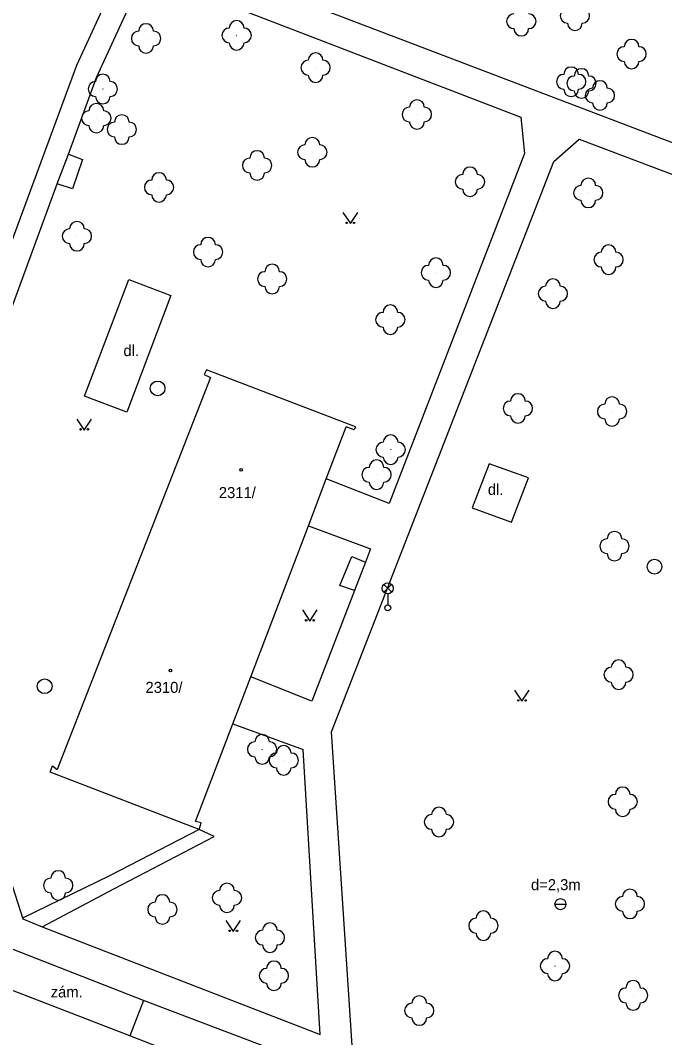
# Model space of a CAD drawing. Extents: x -737812 to -729375, y -1123000 to -1115500.
# Drawn here: x -736618.5 to -736574.7, y -1118642.1 to -1118573.1 of the extents above; entities that cross this region are included whole.
import ezdxf

# ---------------------------------------------------------------- set-up
doc = ezdxf.new("R2010")
doc.units = 0
for name, color, linetype in [('Doplněk polohopisu', 7, 'Continuous'), ('Doplňkové značky', 7, 'Continuous'), ('Komunikace', 7, 'Continuous'), ('Pomocné popisy', 7, 'Continuous'), ('Povr_ zn_ inž_ sítí - el_', 7, 'Continuous'), ('Povr_ zn_ inž_ sítí - kan_', 7, 'Continuous'), ('Stavební objekty', 7, 'Continuous'), ('Zeleň', 7, 'Continuous'), ('Značky druhů budov', 7, 'Continuous'), ('Značky druhů pozemků', 7, 'Continuous'), ('Čísla popisná', 7, 'Continuous')]:
    doc.layers.add(name, color=color, linetype=linetype)

msp = doc.modelspace()

# ---------------------------------------------------------------- linework, layer by layer
at = {"layer": 'Doplněk polohopisu'}
for p, q in [((-736613.29, -1118576.93), (-736610.8, -1118571.51)), ((-736615.21, -1118582.13), (-736613.29, -1118576.93)), ((-736615.96, -1118584.14), (-736615.21, -1118582.13)), ((-736625.78, -1118610.65), (-736615.96, -1118584.14)), ((-736598.91, -1118607.35), (-736594.68, -1118608.93)), ((-736594.68, -1118608.93), (-736595.02, -1118609.82)), ((-736595.02, -1118609.82), (-736595.78, -1118611.76)), ((-736625.78, -1118610.65), (-736618.31, -1118634.04)), ((-736595.78, -1118611.76), (-736598.67, -1118619.25)), ((-736598.67, -1118619.25), (-736602.82, -1118617.61)), ((-736598.11, -1118641.88), (-736599.27, -1118622.55)), ((-736618.31, -1118634.04), (-736617, -1118634.57)), ((-736617, -1118634.57), (-736598.11, -1118641.88)), ((-736597.79, -1118644.24), (-736610.11, -1118639.58)), ((-736598.73, -1118646.75), (-736611.04, -1118641.97))]:
    msp.add_line(p, q, dxfattribs=at)
for points in [[(-736611.83, -1118565.83), (-736611.08, -1118566.66), (-736610.89, -1118567.95), (-736614.66, -1118576.12), (-736617.94, -1118585), (-736626.76, -1118608.86)], [(-736573.82, -1118581.5), (-736600.76, -1118571.22)], [(-736605.73, -1118571.43), (-736584.49, -1118579.63), (-736584.22, -1118582.09), (-736593.43, -1118605.85), (-736597.7, -1118604.18)], [(-736595.94, -1118642.63), (-736597.33, -1118621.34), (-736582.25, -1118582.62), (-736580.51, -1118581.12), (-736573.74, -1118583.67)], [(-736615.21, -1118582.13), (-736614.24, -1118582.49), (-736614.92, -1118584.49), (-736615.96, -1118584.14)], [(-736611.25, -1118599.64), (-736614.12, -1118598.55), (-736611.11, -1118590.63), (-736608.24, -1118591.73), (-736611.25, -1118599.64)], [(-736587.78, -1118606.13), (-736585.11, -1118607.11), (-736583.97, -1118604.11), (-736586.62, -1118603.16), (-736587.78, -1118606.13)], [(-736595.78, -1118611.76), (-736596.77, -1118611.42), (-736595.95, -1118609.44), (-736595.02, -1118609.82)], [(-736604.04, -1118620.81), (-736599.27, -1118622.55)], [(-736617, -1118634.57), (-736612.08, -1118631.98), (-736605.3, -1118628.44), (-736606.32, -1118627.98), (-736612.41, -1118631.12), (-736618.33, -1118633.99)], [(-736610.11, -1118639.58), (-736611.04, -1118641.97)]]:
    msp.add_lwpolyline(points, dxfattribs=at)
at = {"layer": 'Doplňkové značky'}
msp.add_line((-736582.165, -1118633.04), (-736581.415, -1118633.04), dxfattribs=at)
msp.add_circle((-736581.79, -1118633.04), 0.375, dxfattribs=at)
at = {"layer": 'Komunikace'}
for points in [[(-736610.11, -1118639.58), (-736618.95, -1118636.11)], [(-736611.04, -1118641.97), (-736619.91, -1118638.55)]]:
    msp.add_lwpolyline(points, dxfattribs=at)
at = {"layer": 'Povr_ zn_ inž_ sítí - el_'}
for p, q in [((-736593.784, -1118611.868), (-736593.256, -1118611.34)), ((-736593.248, -1118611.865), (-736593.776, -1118611.336)), ((-736593.52, -1118611.98), (-736593.52, -1118612.73))]:
    msp.add_line(p, q, dxfattribs=at)
for centre, radius in [((-736593.52, -1118611.605), 0.375), ((-736593.52, -1118612.93), 0.2)]:
    msp.add_circle(centre, radius, dxfattribs=at)
at = {"layer": 'Povr_ zn_ inž_ sítí - kan_'}
for centre in [(-736609.15, -1118598.03), (-736575.4, -1118610.13), (-736616.82, -1118618.25)]:
    msp.add_circle(centre, 0.5, dxfattribs=at)
at = {"layer": 'Stavební objekty'}
for points in [[(-736605.84, -1118596.78), (-736605.99, -1118597.08)], [(-736595.7, -1118600.65), (-736605.84, -1118596.78)], [(-736605.56, -1118597.3), (-736615.97, -1118623.9)], [(-736605.99, -1118597.08), (-736605.56, -1118597.3)], [(-736606.57, -1118627.43), (-736604.04, -1118620.81), (-736602.82, -1118617.61), (-736598.91, -1118607.35), (-736597.7, -1118604.18), (-736596.34, -1118600.64)], [(-736595.79, -1118600.85), (-736596.34, -1118600.64)], [(-736595.7, -1118600.65), (-736595.79, -1118600.85)], [(-736616.45, -1118624.08), (-736616.29, -1118623.66)], [(-736616.29, -1118623.66), (-736615.97, -1118623.9)], [(-736606.32, -1118627.98), (-736616.45, -1118624.08)], [(-736606.19, -1118627.53), (-736606.57, -1118627.43)], [(-736606.32, -1118627.98), (-736606.19, -1118627.53)]]:
    msp.add_lwpolyline(points, dxfattribs=at)
at = {"layer": 'Zeleň'}
for centre in [(-736584.45, -1118573.11), (-736603.78, -1118574.07), (-736609.93, -1118574.28), (-736576.96, -1118575.34), (-736598.42, -1118576.26), (-736581.06, -1118577.22), (-736580.36, -1118577.33), (-736612.87, -1118577.71), (-736579.11, -1118578.15), (-736591.54, -1118579.44), (-736613.31, -1118579.69), (-736611.58, -1118580.46), (-736598.64, -1118582), (-736602.39, -1118582.9), (-736609.05, -1118584.39), (-736587.93, -1118584.01), (-736579.9, -1118584.76), (-736614.63, -1118587.7), (-736605.72, -1118588.78), (-736578.52, -1118589.29), (-736601.37, -1118590.61), (-736590.25, -1118590.18), (-736582.3, -1118591.6), (-736593.34, -1118593.37), (-736584.68, -1118599.39), (-736578.28, -1118599.6), (-736593.32, -1118602.19), (-736594.28, -1118603.89), (-736578.12, -1118608.74), (-736577.84, -1118617.46), (-736602.05, -1118622.53), (-736600.58, -1118623.28), (-736577.56, -1118626.09), (-736590.04, -1118627.46), (-736615.9, -1118631.77), (-736604.44, -1118632.61), (-736608.82, -1118633.4), (-736577.07, -1118633.02), (-736587.02, -1118634.5), (-736601.52, -1118635.31), (-736582.16, -1118637.24), (-736601.25, -1118637.9), (-736576.85, -1118639.23), (-736591.38, -1118640.26)]:
    msp.add_circle(centre, 0.0005, dxfattribs=at)
for centre, start, end in [((-736584.95, -1118573.11), 89.99999, 269.99999), ((-736583.95, -1118573.11), 270, 89.99999), ((-736581.31, -1118572.74), 89.99999, 269.99999), ((-736580.31, -1118572.74), 270, 89.99999), ((-736609.93, -1118573.78), 0, 179.99999), ((-736603.78, -1118573.57), 360, 179.99999), ((-736580.81, -1118573.24), 179.99999, 359.99999), ((-736610.43, -1118574.28), 89.99999, 269.99999), ((-736609.43, -1118574.28), 270, 89.99999), ((-736604.28, -1118574.07), 89.99999, 269.99999), ((-736603.28, -1118574.07), 270, 89.99999), ((-736584.45, -1118573.61), 179.99999, 359.99999), ((-736609.93, -1118574.78), 179.99999, 359.99999), ((-736603.78, -1118574.57), 179.99999, 359.99999), ((-736576.96, -1118574.84), 360, 179.99999), ((-736598.42, -1118575.76), 360, 179.99999), ((-736577.46, -1118575.34), 89.99999, 269.99999), ((-736576.46, -1118575.34), 270, 89.99999), ((-736598.92, -1118576.26), 89.99999, 269.99999), ((-736597.92, -1118576.26), 270, 89.99999), ((-736576.96, -1118575.84), 179.99999, 359.99999), ((-736612.87, -1118577.21), 360, 179.99999), ((-736598.42, -1118576.76), 179.99999, 359.99999), ((-736581.56, -1118577.22), 89.99999, 269.99999), ((-736581.06, -1118576.72), 360, 179.99999), ((-736580.86, -1118577.33), 89.99999, 269.99999), ((-736580.36, -1118576.83), 360, 179.99999), ((-736580.56, -1118577.22), 270, 89.99999), ((-736579.86, -1118577.33), 270, 89.99999), ((-736613.37, -1118577.71), 89.99999, 269.99999), ((-736612.37, -1118577.71), 270, 89.99999), ((-736579.11, -1118577.65), 360, 179.99999), ((-736612.87, -1118578.21), 179.99999, 359.99999), ((-736581.06, -1118577.72), 179.99999, 359.99999), ((-736580.36, -1118577.83), 179.99999, 359.99999), ((-736579.61, -1118578.15), 89.99999, 269.99999), ((-736578.61, -1118578.15), 270, 89.99999), ((-736613.31, -1118579.19), 360, 179.99999), ((-736591.54, -1118578.94), 360, 179.99999), ((-736579.11, -1118578.65), 179.99999, 359.99999), ((-736613.81, -1118579.69), 89.99999, 269.99999), ((-736612.81, -1118579.69), 270, 89.99999), ((-736611.58, -1118579.96), 0, 179.99999), ((-736592.04, -1118579.44), 89.99999, 269.99999), ((-736591.04, -1118579.44), 270, 89.99999), ((-736613.31, -1118580.19), 179.99999, 359.99999), ((-736612.08, -1118580.46), 89.99999, 269.99999), ((-736611.08, -1118580.46), 270, 89.99999), ((-736591.54, -1118579.94), 179.99999, 359.99999), ((-736611.58, -1118580.96), 179.99999, 359.99999), ((-736599.14, -1118582), 89.99999, 269.99999), ((-736598.64, -1118581.5), 360, 179.99999), ((-736598.14, -1118582), 270, 89.99999), ((-736602.39, -1118582.4), 360, 179.99999), ((-736602.89, -1118582.9), 89.99999, 269.99999), ((-736601.89, -1118582.9), 270, 89.99999), ((-736598.64, -1118582.5), 179.99999, 359.99999), ((-736587.93, -1118583.51), 360, 179.99999), ((-736609.05, -1118583.89), 360, 179.99999), ((-736602.39, -1118583.4), 179.99999, 359.99999), ((-736588.43, -1118584.01), 89.99999, 269.99999), ((-736587.43, -1118584.01), 270, 89.99999), ((-736579.9, -1118584.26), 360, 179.99999), ((-736609.55, -1118584.39), 89.99999, 269.99999), ((-736608.55, -1118584.39), 270, 89.99999), ((-736580.4, -1118584.76), 89.99999, 269.99999), ((-736579.4, -1118584.76), 270, 89.99999), ((-736609.05, -1118584.89), 179.99999, 359.99999), ((-736587.93, -1118584.51), 179.99999, 359.99999), ((-736579.9, -1118585.26), 179.99999, 359.99999), ((-736615.13, -1118587.7), 89.99999, 269.99999), ((-736614.63, -1118587.2), 0, 179.99999), ((-736614.13, -1118587.7), 270, 89.99999), ((-736605.72, -1118588.28), 0, 179.99999), ((-736614.63, -1118588.2), 179.99999, 359.99999), ((-736606.22, -1118588.78), 89.99999, 269.99999), ((-736605.22, -1118588.78), 270, 89.99999), ((-736578.52, -1118588.79), 360, 179.99999), ((-736605.72, -1118589.28), 179.99999, 359.99999), ((-736590.25, -1118589.68), 360, 179.99999), ((-736579.02, -1118589.29), 89.99999, 269.99999), ((-736578.02, -1118589.29), 270, 89.99999), ((-736601.37, -1118590.11), 0, 179.99999), ((-736590.75, -1118590.18), 89.99999, 269.99999), ((-736589.75, -1118590.18), 270, 89.99999), ((-736578.52, -1118589.79), 179.99999, 359.99999), ((-736601.87, -1118590.61), 89.99999, 269.99999), ((-736600.87, -1118590.61), 270, 89.99999), ((-736582.3, -1118591.1), 360, 179.99999), ((-736601.37, -1118591.11), 179.99999, 359.99999), ((-736590.25, -1118590.68), 179.99999, 359.99999), ((-736582.8, -1118591.6), 89.99999, 269.99999), ((-736581.8, -1118591.6), 270, 89.99999), ((-736593.34, -1118592.87), 360, 179.99999), ((-736582.3, -1118592.1), 179.99999, 359.99999), ((-736593.84, -1118593.37), 89.99999, 269.99999), ((-736592.84, -1118593.37), 270, 89.99999), ((-736593.34, -1118593.87), 179.99999, 359.99999), ((-736585.18, -1118599.39), 89.99999, 269.99999), ((-736584.68, -1118598.89), 360, 179.99999), ((-736584.18, -1118599.39), 270, 89.99999), ((-736578.28, -1118599.1), 360, 179.99999), ((-736578.78, -1118599.6), 89.99999, 269.99999), ((-736577.78, -1118599.6), 270, 89.99999), ((-736584.68, -1118599.89), 179.99999, 359.99999), ((-736578.28, -1118600.1), 179.99999, 359.99999), ((-736593.82, -1118602.19), 89.99999, 269.99999), ((-736593.32, -1118601.69), 360, 179.99999), ((-736592.82, -1118602.19), 270, 89.99999), ((-736594.28, -1118603.39), 360, 179.99999), ((-736593.32, -1118602.69), 179.99999, 359.99999), ((-736594.78, -1118603.89), 89.99999, 269.99999), ((-736593.78, -1118603.89), 270, 89.99999), ((-736594.28, -1118604.39), 179.99999, 359.99999), ((-736578.12, -1118608.24), 360, 179.99999), ((-736578.62, -1118608.74), 89.99999, 269.99999), ((-736577.62, -1118608.74), 270, 89.99999), ((-736578.12, -1118609.24), 179.99999, 359.99999), ((-736577.84, -1118616.96), 360, 179.99999), ((-736578.34, -1118617.46), 89.99999, 269.99999), ((-736577.34, -1118617.46), 270, 89.99999), ((-736577.84, -1118617.96), 179.99999, 359.99999), ((-736602.05, -1118622.03), 360, 179.99999), ((-736602.55, -1118622.53), 89.99999, 269.99999), ((-736601.55, -1118622.53), 270, 89.99999), ((-736600.58, -1118622.78), 360, 179.99999), ((-736602.05, -1118623.03), 179.99999, 359.99999), ((-736601.08, -1118623.28), 89.99999, 269.99999), ((-736600.08, -1118623.28), 270, 89.99999), ((-736600.58, -1118623.78), 179.99999, 359.99999), ((-736577.56, -1118625.59), 360, 179.99999), ((-736578.06, -1118626.09), 89.99999, 269.99999), ((-736577.06, -1118626.09), 270, 89.99999), ((-736590.04, -1118626.96), 360, 179.99999), ((-736590.54, -1118627.46), 89.99999, 269.99999), ((-736589.54, -1118627.46), 270, 89.99999), ((-736577.56, -1118626.59), 179.99999, 359.99999), ((-736590.04, -1118627.96), 179.99999, 359.99999), ((-736616.4, -1118631.77), 89.99999, 269.99999), ((-736615.9, -1118631.27), 360, 179.99999), ((-736615.4, -1118631.77), 270, 89.99999), ((-736604.44, -1118632.11), 360, 179.99999), ((-736577.07, -1118632.52), 360, 179.99999), ((-736615.9, -1118632.27), 179.99999, 359.99999), ((-736608.82, -1118632.9), 360, 179.99999), ((-736604.94, -1118632.61), 89.99999, 269.99999), ((-736603.94, -1118632.61), 270, 89.99999), ((-736577.57, -1118633.02), 89.99999, 269.99999), ((-736576.57, -1118633.02), 270, 89.99999), ((-736609.32, -1118633.4), 89.99999, 269.99999), ((-736608.32, -1118633.4), 270, 89.99999), ((-736604.44, -1118633.11), 179.99999, 359.99999), ((-736608.82, -1118633.9), 179.99999, 359.99999), ((-736587.52, -1118634.5), 89.99999, 269.99999), ((-736587.02, -1118634), 360, 179.99999), ((-736586.52, -1118634.5), 270, 89.99999), ((-736577.07, -1118633.52), 179.99999, 359.99999), ((-736602.02, -1118635.31), 89.99999, 269.99999), ((-736601.52, -1118634.81), 360, 179.99999), ((-736601.02, -1118635.31), 270, 89.99999), ((-736587.02, -1118635), 179.99999, 359.99999), ((-736601.52, -1118635.81), 179.99999, 359.99999), ((-736601.25, -1118637.4), 360, 179.99999), ((-736582.66, -1118637.24), 89.99999, 269.99999), ((-736582.16, -1118636.74), 360, 179.99999), ((-736581.66, -1118637.24), 270, 89.99999), ((-736601.75, -1118637.9), 89.99999, 269.99999), ((-736600.75, -1118637.9), 270, 89.99999), ((-736582.16, -1118637.74), 179.99999, 359.99999), ((-736576.85, -1118638.73), 360, 179.99999), ((-736601.25, -1118638.4), 179.99999, 359.99999), ((-736577.35, -1118639.23), 89.99999, 269.99999), ((-736576.35, -1118639.23), 270, 89.99999), ((-736591.38, -1118639.76), 360, 179.99999), ((-736591.88, -1118640.26), 89.99999, 269.99999), ((-736590.88, -1118640.26), 270, 89.99999), ((-736576.85, -1118639.73), 179.99999, 359.99999), ((-736591.38, -1118640.76), 179.99999, 359.99999)]:
    msp.add_arc(centre, 0.5, start, end, dxfattribs=at)
at = {"layer": 'Značky druhů budov'}
for centre in [(-736603.48, -1118603.56), (-736608.28, -1118617.18)]:
    msp.add_circle(centre, 0.0875, dxfattribs=at)
at = {"layer": 'Značky druhů pozemků'}
for points in [[(-736596.56, -1118586.1), (-736596.06, -1118586.85), (-736595.56, -1118586.1)], [(-736614.63, -1118600.11), (-736614.13, -1118600.86), (-736613.63, -1118600.11)], [(-736599.31, -1118613.07), (-736598.81, -1118613.82), (-736598.31, -1118613.07)], [(-736584.91, -1118618.51), (-736584.41, -1118619.26), (-736583.91, -1118618.51)], [(-736604.51, -1118634.15), (-736604.01, -1118634.9), (-736603.51, -1118634.15)]]:
    msp.add_lwpolyline(points, dxfattribs=at)
for centre in [(-736596.311, -1118586.799), (-736595.811, -1118586.799), (-736614.38, -1118600.81), (-736613.88, -1118600.81), (-736599.06, -1118613.77), (-736598.56, -1118613.77), (-736584.66, -1118619.21), (-736584.16, -1118619.21), (-736604.26, -1118634.85), (-736603.76, -1118634.85)]:
    msp.add_circle(centre, 0.05, dxfattribs=at)

# ---------------------------------------------------------------- texts
at = {"layer": 'Pomocné popisy'}
for s, p in [('dl.', (-736611.47, -1118595.84)), ('dl.', (-736586.72, -1118605.26)), ('d=2,3m', (-736583.79, -1118632.09)), ('zám.', (-736616.41, -1118639.37))]:
    msp.add_text(s, height=0.75, dxfattribs=at).set_placement(p)
at = {"layer": 'Čísla popisná'}
for s, p in [('2311/', (-736604.99, -1118605.48)), ('2310/', (-736609.97, -1118618.7))]:
    msp.add_text(s, height=0.75, dxfattribs=at).set_placement(p)

doc.saveas('drawing.dxf')
